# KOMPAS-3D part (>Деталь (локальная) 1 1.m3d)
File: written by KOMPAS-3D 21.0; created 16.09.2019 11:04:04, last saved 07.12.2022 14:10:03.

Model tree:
1. Эскиз:1
2. Элемент выдавливания:1
     Расстояние 1 = 10
3. Эскиз:2  (with: Элемент выдавливания:1)
4. Элемент выдавливания:2
     Расстояние 2 = 10
5. Эскиз:3  (with: Элемент выдавливания:1)
6. Элемент выдавливания:3
     Расстояние 2 = 10
7. Эскиз:4  (with: Элемент выдавливания:1)
8. Элемент выдавливания:4
     Расстояние 2 = 10

Referenced files in C:\PDM_TEST\Проекты МО\71.17 ОНПЗ\81.47.00.000 М-266\81.47.00.500 Питатель вибрац\: Сборка.a3d
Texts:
  Штрихпунктирная 2 ум 4
  Штрихпунктирная 2 ум 2
  Штрихпунктирная 2
  Штриховая ум 4
  Штриховая ум 2
  Осевая ув 2
  Осевая ум 4
  Осевая ум 2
